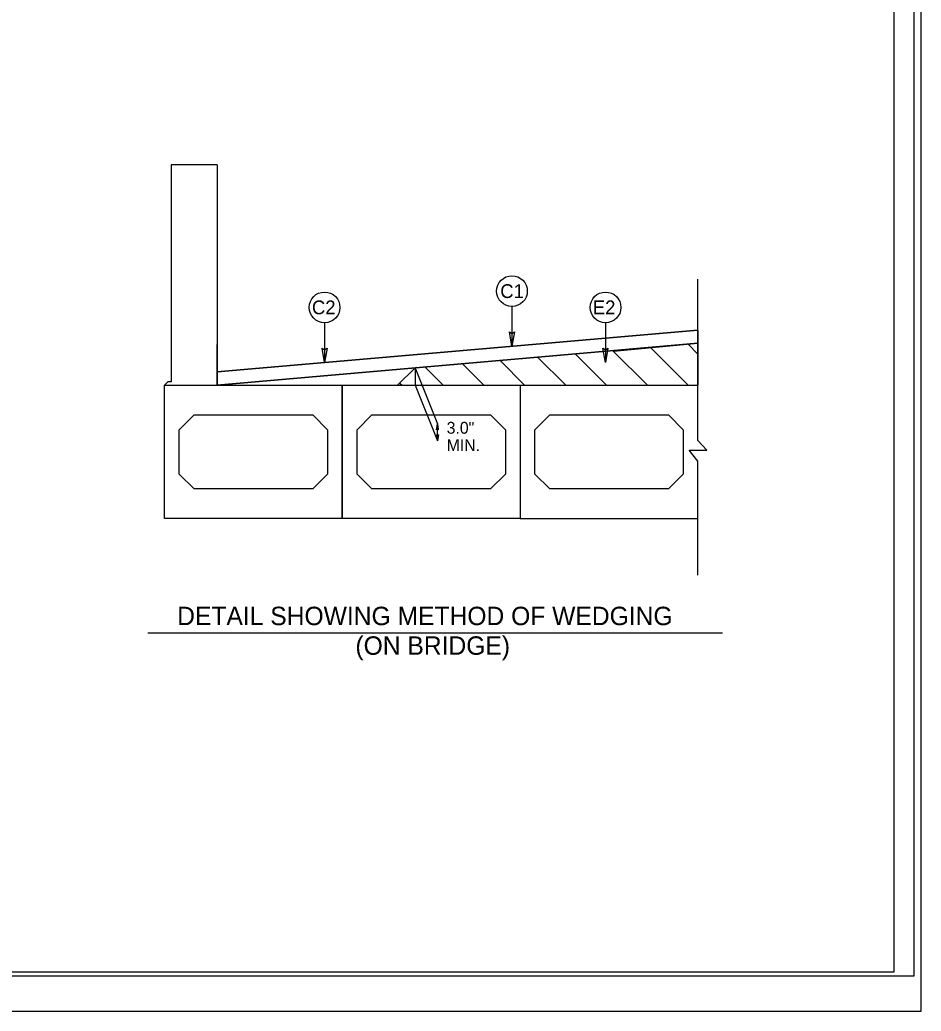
# Model space of a CAD drawing. Extents: x 1542177 to 1542464, y 45134 to 45344.
# Drawn here: x 1542315.1 to 1542360.7, y 45134.4 to 45184.6 of the extents above; entities that cross this region are included whole.
import ezdxf

# ---------------------------------------------------------------- set-up
doc = ezdxf.new("R2010")
doc.units = 0
for name, color, linetype in [('Default', 7, 'Continuous'), ('Old_Level_1', 7, 'Continuous'), ('Prop Dimension Text', 7, 'Continuous'), ('Sheet Cutting Line CELL', 7, 'Continuous'), ('Sheet Plot Border Inside CELL', 7, 'Continuous'), ('Sheet Plot Border Outside CELL', 7, 'Continuous'), ('Sheet Typical CELL', 7, 'Continuous'), ('Typical Detail Wedge3 CELL', 7, 'Continuous'), ('Typical Text Label CELL', 7, 'Continuous')]:
    doc.layers.add(name, color=color, linetype=linetype)

# ---------------------------------------------------------------- blocks, each defined once
blk = doc.blocks.new('CIR')
at = {"layer": 'Default'}
blk.add_line((0, 1.914), (0, 0), dxfattribs=at)
blk.add_lwpolyline([(0.118, 0.686), (0, 0), (-0.122, 0.69), (0, 0.602)], close=True, dxfattribs=at)
blk.add_circle((0, 2.654), 0.741, dxfattribs=at)

msp = doc.modelspace()

# ---------------------------------------------------------------- linework, layer by layer
at = {"layer": 'Old_Level_1'}
for p, q in [((1542325.095, 45177.306), (1542322.765, 45177.305)), ((1542322.765, 45177.305), (1542322.767, 45166.314)), ((1542325.095, 45177.306), (1542325.094, 45166.143)), ((1542349.43, 45163.343), (1542349.43, 45171.518)), ((1542349.417, 45168.94), (1542325.09, 45166.829)), ((1542349.421, 45168.267), (1542349.417, 45168.94)), ((1542349.421, 45168.267), (1542325.094, 45166.156)), ((1542325.094, 45166.156), (1542349.421, 45168.267)), ((1542335.111, 45167.026), (1542349.421, 45168.267)), ((1542334.227, 45166.143), (1542335.111, 45167.026)), ((1542325.09, 45166.829), (1542325.094, 45166.156)), ((1542322.595, 45166.314), (1542322.424, 45166.143)), ((1542322.767, 45166.314), (1542322.595, 45166.314)), ((1542340.428, 45166.143), (1542349.43, 45166.143)), ((1542323.174, 45163.892), (1542323.924, 45164.643)), ((1542323.924, 45164.643), (1542329.926, 45164.643)), ((1542329.926, 45164.643), (1542330.676, 45163.892)), ((1542332.176, 45163.892), (1542332.926, 45164.643)), ((1542332.926, 45164.643), (1542338.928, 45164.643)), ((1542338.928, 45164.643), (1542339.678, 45163.892)), ((1542341.178, 45163.892), (1542341.929, 45164.643)), ((1542341.929, 45164.643), (1542347.93, 45164.643)), ((1542347.93, 45164.643), (1542348.68, 45163.892)), ((1542323.174, 45161.642), (1542323.174, 45163.892)), ((1542330.676, 45163.892), (1542330.676, 45161.642)), ((1542332.176, 45161.642), (1542332.176, 45163.892)), ((1542339.678, 45163.892), (1542339.678, 45161.642)), ((1542341.178, 45161.642), (1542341.178, 45163.892)), ((1542348.68, 45163.892), (1542348.68, 45161.642)), ((1542349.43, 45156.524), (1542349.43, 45162.298)), ((1542323.924, 45160.892), (1542323.174, 45161.642)), ((1542330.676, 45161.642), (1542329.926, 45160.892)), ((1542332.926, 45160.892), (1542332.176, 45161.642)), ((1542339.678, 45161.642), (1542338.928, 45160.892)), ((1542341.929, 45160.892), (1542341.178, 45161.642)), ((1542348.68, 45161.642), (1542347.93, 45160.892)), ((1542329.926, 45160.892), (1542323.924, 45160.892)), ((1542338.928, 45160.892), (1542332.926, 45160.892)), ((1542347.93, 45160.892), (1542341.929, 45160.892)), ((1542340.428, 45159.391), (1542349.43, 45159.391))]:
    msp.add_line(p, q, dxfattribs=at)
for points in [[(1542322.424, 45166.143), (1542331.426, 45166.143), (1542331.426, 45159.391), (1542322.424, 45159.391)], [(1542331.426, 45166.143), (1542340.428, 45166.143), (1542340.428, 45159.391), (1542331.426, 45159.391)]]:
    msp.add_lwpolyline(points, close=True, dxfattribs=at)
for points in [[(1542348.982, 45162.849), (1542349.886, 45162.849), (1542349.43, 45163.343)], [(1542349.43, 45156.524), (1542349.43, 45162.298), (1542348.982, 45162.849)]]:
    msp.add_lwpolyline(points, dxfattribs=at)
at = {"layer": 'Prop Dimension Text'}
msp.add_line((1542321.58, 45153.605), (1542350.668, 45153.605), dxfattribs=at)
at = {"layer": 'Sheet Cutting Line CELL'}
msp.add_line((1542226.007, 45134.448), (1542360.727, 45134.448), dxfattribs=at)
at = {"layer": 'Sheet Plot Border Inside CELL'}
msp.add_lwpolyline([(1542360.367, 45220.652), (1542227.047, 45220.652), (1542227.047, 45136.244), (1542360.367, 45136.244)], close=True, dxfattribs=at)
at = {"layer": 'Sheet Plot Border Outside CELL'}
msp.add_lwpolyline([(1542360.727, 45222.448), (1542226.007, 45222.448), (1542226.007, 45134.448), (1542360.727, 45134.448)], close=True, dxfattribs=at)
at = {"layer": 'Sheet Typical CELL'}
msp.add_lwpolyline([(1542359.367, 45220.448), (1542239.367, 45220.448), (1542239.367, 45136.448), (1542359.367, 45136.448)], close=True, dxfattribs=at)
at = {"layer": 'Typical Detail Wedge3 CELL'}
for p, q in [((1542325.09, 45166.829), (1542349.417, 45168.94)), ((1542349.417, 45168.94), (1542349.421, 45168.267)), ((1542325.095, 45166.183), (1542325.083, 45168.201)), ((1542345.15, 45167.875), (1542349.421, 45168.267)), ((1542347.031, 45168.047), (1542348.935, 45166.144)), ((1542348.926, 45168.221), (1542349.423, 45167.724)), ((1542349.421, 45168.267), (1542349.43, 45166.144)), ((1542341.311, 45167.563), (1542342.733, 45166.143)), ((1542343.215, 45167.728), (1542344.799, 45166.144)), ((1542345.117, 45167.893), (1542346.866, 45166.144)), ((1542335.111, 45167.026), (1542335.111, 45166.144)), ((1542335.135, 45166.974), (1542336.24, 45164.193)), ((1542335.601, 45167.068), (1542336.529, 45166.14)), ((1542337.505, 45167.233), (1542338.579, 45166.16)), ((1542339.408, 45167.398), (1542340.669, 45166.137)), ((1542325.094, 45166.143), (1542349.43, 45166.144)), ((1542334.344, 45166.256), (1542334.454, 45166.146)), ((1542335.111, 45166.144), (1542336.241, 45163.335)), ((1542336.241, 45163.335), (1542336.24, 45164.192))]:
    msp.add_line(p, q, dxfattribs=at)
for points in [[(1542336.188, 45163.893), (1542336.24, 45163.932), (1542336.294, 45163.893), (1542336.24, 45164.193), (1542336.279, 45163.904), (1542336.264, 45163.915), (1542336.24, 45164.193), (1542336.248, 45163.927), (1542336.24, 45163.932), (1542336.24, 45164.193), (1542336.226, 45163.921), (1542336.211, 45163.91), (1542336.24, 45164.193), (1542336.195, 45163.899), (1542336.188, 45163.893), (1542336.24, 45164.193)], [(1542336.294, 45163.634), (1542336.241, 45163.595), (1542336.188, 45163.634), (1542336.241, 45163.335), (1542336.203, 45163.623), (1542336.218, 45163.612), (1542336.241, 45163.335), (1542336.233, 45163.601), (1542336.241, 45163.595), (1542336.241, 45163.335), (1542336.256, 45163.606), (1542336.271, 45163.618), (1542336.241, 45163.335), (1542336.286, 45163.629), (1542336.294, 45163.634), (1542336.241, 45163.335)]]:
    msp.add_lwpolyline(points, dxfattribs=at)

# ---------------------------------------------------------------- block references
at = {"layer": 'Default', "xscale": 1.0498642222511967, "yscale": 1.0498642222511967}
for p in [(1542340.013, 45168.124), (1542330.529, 45167.3), (1542344.749, 45167.3)]:
    msp.add_blockref('CIR', p, dxfattribs=at)

# ---------------------------------------------------------------- texts
at = {"layer": 'Default'}
for s, p in [('C1', (1542339.422, 45170.561)), ('C2', (1542329.889, 45169.738)), ('E2', (1542344.108, 45169.738))]:
    msp.add_text(s, height=0.6982, dxfattribs=at).set_placement(p)
at = {"layer": 'Typical Detail Wedge3 CELL'}
for s, p in [('3.0"', (1542336.706, 45163.689)), ('MIN.', (1542336.706, 45162.81))]:
    msp.add_text(s, height=0.6, dxfattribs=at).set_placement(p)
at = {"layer": 'Typical Text Label CELL'}
for s, p in [('DETAIL SHOWING METHOD OF WEDGING', (1542323.067, 45153.996)), ('(ON BRIDGE)', (1542332.089, 45152.495))]:
    msp.add_text(s, height=0.93247, rotation=360, dxfattribs=at).set_placement(p)

doc.saveas('drawing.dxf')
